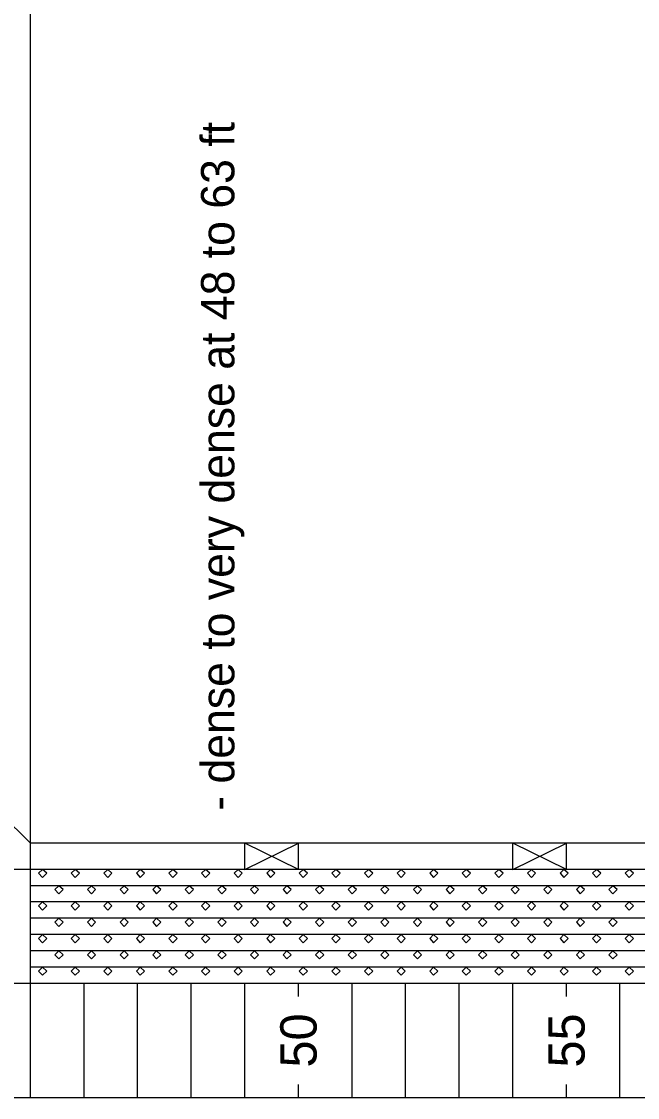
# Model space of a CAD drawing. Extents: x 1313964 to 1316843, y 2087046 to 2096619.
# Drawn here: x 1314089.13 to 1314100.62, y 2089873.43 to 2089893.52 of the extents above; entities that cross this region are included whole.
import ezdxf

# ---------------------------------------------------------------- set-up
doc = ezdxf.new("R2010")
doc.units = 0
doc.layers.add('B-Sub-Contour', color=7, linetype='Continuous')

msp = doc.modelspace()

# ---------------------------------------------------------------- linework, layer by layer
at = {"layer": 'B-Sub-Contour'}
for points in [[(1314136.725, 2089873.434), (1314136.725, 2089916.306), (1314075.306, 2089916.306), (1314075.306, 2089873.434), (1314136.725, 2089873.434)], [(1314089.292, 2089873.434), (1314089.292, 2089916.306)], [(1314089.292, 2089878.178), (1314088.745, 2089878.725)], [(1314134.292, 2089878.178), (1314089.292, 2089878.178)], [(1314093.292, 2089877.691), (1314094.292, 2089878.178)], [(1314094.292, 2089877.691), (1314093.292, 2089878.178)], [(1314093.292, 2089877.691), (1314093.292, 2089878.178)], [(1314094.292, 2089877.691), (1314094.292, 2089878.178)], [(1314098.292, 2089877.691), (1314099.292, 2089878.178)], [(1314099.292, 2089877.691), (1314098.292, 2089878.178)], [(1314098.292, 2089877.691), (1314098.292, 2089878.178)], [(1314099.292, 2089877.691), (1314099.292, 2089878.178)], [(1314134.292, 2089877.691), (1314082.603, 2089877.691)], [(1314112.292, 2089877.387), (1314089.292, 2089877.387)], [(1314112.292, 2089877.083), (1314089.292, 2089877.083)], [(1314112.292, 2089876.779), (1314089.292, 2089876.779)], [(1314112.292, 2089876.475), (1314089.292, 2089876.475)], [(1314112.292, 2089876.171), (1314089.292, 2089876.171)], [(1314112.292, 2089875.867), (1314089.292, 2089875.867)], [(1314134.292, 2089875.563), (1314082.603, 2089875.563)], [(1314089.292, 2089875.319), (1314089.292, 2089875.563)], [(1314090.292, 2089873.434), (1314090.292, 2089875.563)], [(1314090.292, 2089873.434), (1314090.292, 2089875.563)], [(1314091.292, 2089873.434), (1314091.292, 2089875.563)], [(1314092.292, 2089873.434), (1314092.292, 2089875.563)], [(1314092.292, 2089873.434), (1314092.292, 2089875.563)], [(1314093.292, 2089873.434), (1314093.292, 2089875.563)], [(1314094.292, 2089875.319), (1314094.292, 2089875.563)], [(1314094.292, 2089875.319), (1314094.292, 2089875.563)], [(1314095.292, 2089873.434), (1314095.292, 2089875.563)], [(1314096.292, 2089873.434), (1314096.292, 2089875.563)], [(1314096.292, 2089873.434), (1314096.292, 2089875.563)], [(1314097.292, 2089873.434), (1314097.292, 2089875.563)], [(1314098.292, 2089873.434), (1314098.292, 2089875.563)], [(1314098.292, 2089873.434), (1314098.292, 2089875.563)], [(1314099.292, 2089875.319), (1314099.292, 2089875.563)], [(1314100.292, 2089873.434), (1314100.292, 2089875.563)], [(1314100.292, 2089873.434), (1314100.292, 2089875.563)], [(1314089.292, 2089873.434), (1314089.292, 2089873.678)], [(1314094.292, 2089873.434), (1314094.292, 2089873.678)], [(1314094.292, 2089873.434), (1314094.292, 2089873.678)], [(1314099.292, 2089873.434), (1314099.292, 2089873.678)]]:
    msp.add_lwpolyline(points, dxfattribs=at)
for points in [[(1314089.517, 2089877.691), (1314089.444, 2089877.618), (1314089.517, 2089877.539), (1314089.597, 2089877.618)], [(1314090.126, 2089877.691), (1314090.053, 2089877.618), (1314090.126, 2089877.539), (1314090.205, 2089877.618)], [(1314090.734, 2089877.691), (1314090.661, 2089877.618), (1314090.734, 2089877.539), (1314090.813, 2089877.618)], [(1314091.342, 2089877.691), (1314091.269, 2089877.618), (1314091.342, 2089877.539), (1314091.421, 2089877.618)], [(1314091.95, 2089877.691), (1314091.877, 2089877.618), (1314091.95, 2089877.539), (1314092.029, 2089877.618)], [(1314092.558, 2089877.691), (1314092.485, 2089877.618), (1314092.558, 2089877.539), (1314092.637, 2089877.618)], [(1314093.166, 2089877.691), (1314093.093, 2089877.618), (1314093.166, 2089877.539), (1314093.245, 2089877.618)], [(1314093.774, 2089877.691), (1314093.701, 2089877.618), (1314093.774, 2089877.539), (1314093.853, 2089877.618)], [(1314094.382, 2089877.691), (1314094.309, 2089877.618), (1314094.382, 2089877.539), (1314094.461, 2089877.618)], [(1314094.99, 2089877.691), (1314094.917, 2089877.618), (1314094.99, 2089877.539), (1314095.069, 2089877.618)], [(1314095.599, 2089877.691), (1314095.526, 2089877.618), (1314095.599, 2089877.539), (1314095.678, 2089877.618)], [(1314096.207, 2089877.691), (1314096.134, 2089877.618), (1314096.207, 2089877.539), (1314096.286, 2089877.618)], [(1314096.815, 2089877.691), (1314096.742, 2089877.618), (1314096.815, 2089877.539), (1314096.894, 2089877.618)], [(1314097.423, 2089877.691), (1314097.35, 2089877.618), (1314097.423, 2089877.539), (1314097.502, 2089877.618)], [(1314098.031, 2089877.691), (1314097.958, 2089877.618), (1314098.031, 2089877.539), (1314098.11, 2089877.618)], [(1314098.639, 2089877.691), (1314098.566, 2089877.618), (1314098.639, 2089877.539), (1314098.718, 2089877.618)], [(1314099.247, 2089877.691), (1314099.174, 2089877.618), (1314099.247, 2089877.539), (1314099.326, 2089877.618)], [(1314099.855, 2089877.691), (1314099.782, 2089877.618), (1314099.855, 2089877.539), (1314099.934, 2089877.618)], [(1314100.463, 2089877.691), (1314100.39, 2089877.618), (1314100.463, 2089877.539), (1314100.542, 2089877.618)], [(1314089.822, 2089877.387), (1314089.749, 2089877.314), (1314089.822, 2089877.235), (1314089.901, 2089877.314)], [(1314090.43, 2089877.387), (1314090.357, 2089877.314), (1314090.43, 2089877.235), (1314090.509, 2089877.314)], [(1314091.038, 2089877.387), (1314090.965, 2089877.314), (1314091.038, 2089877.235), (1314091.117, 2089877.314)], [(1314091.646, 2089877.387), (1314091.573, 2089877.314), (1314091.646, 2089877.235), (1314091.725, 2089877.314)], [(1314092.254, 2089877.387), (1314092.181, 2089877.314), (1314092.254, 2089877.235), (1314092.333, 2089877.314)], [(1314092.862, 2089877.387), (1314092.789, 2089877.314), (1314092.862, 2089877.235), (1314092.941, 2089877.314)], [(1314093.47, 2089877.387), (1314093.397, 2089877.314), (1314093.47, 2089877.235), (1314093.549, 2089877.314)], [(1314094.078, 2089877.387), (1314094.005, 2089877.314), (1314094.078, 2089877.235), (1314094.157, 2089877.314)], [(1314094.686, 2089877.387), (1314094.613, 2089877.314), (1314094.686, 2089877.235), (1314094.765, 2089877.314)], [(1314095.294, 2089877.387), (1314095.221, 2089877.314), (1314095.294, 2089877.235), (1314095.374, 2089877.314)], [(1314095.903, 2089877.387), (1314095.83, 2089877.314), (1314095.903, 2089877.235), (1314095.982, 2089877.314)], [(1314096.511, 2089877.387), (1314096.438, 2089877.314), (1314096.511, 2089877.235), (1314096.59, 2089877.314)], [(1314097.119, 2089877.387), (1314097.046, 2089877.314), (1314097.119, 2089877.235), (1314097.198, 2089877.314)], [(1314097.727, 2089877.387), (1314097.654, 2089877.314), (1314097.727, 2089877.235), (1314097.806, 2089877.314)], [(1314098.335, 2089877.387), (1314098.262, 2089877.314), (1314098.335, 2089877.235), (1314098.414, 2089877.314)], [(1314098.943, 2089877.387), (1314098.87, 2089877.314), (1314098.943, 2089877.235), (1314099.022, 2089877.314)], [(1314099.551, 2089877.387), (1314099.478, 2089877.314), (1314099.551, 2089877.235), (1314099.63, 2089877.314)], [(1314100.159, 2089877.387), (1314100.086, 2089877.314), (1314100.159, 2089877.235), (1314100.238, 2089877.314)], [(1314089.517, 2089877.083), (1314089.444, 2089877.01), (1314089.517, 2089876.931), (1314089.597, 2089877.01)], [(1314090.126, 2089877.083), (1314090.053, 2089877.01), (1314090.126, 2089876.931), (1314090.205, 2089877.01)], [(1314090.734, 2089877.083), (1314090.661, 2089877.01), (1314090.734, 2089876.931), (1314090.813, 2089877.01)], [(1314091.342, 2089877.083), (1314091.269, 2089877.01), (1314091.342, 2089876.931), (1314091.421, 2089877.01)], [(1314091.95, 2089877.083), (1314091.877, 2089877.01), (1314091.95, 2089876.931), (1314092.029, 2089877.01)], [(1314092.558, 2089877.083), (1314092.485, 2089877.01), (1314092.558, 2089876.931), (1314092.637, 2089877.01)], [(1314093.166, 2089877.083), (1314093.093, 2089877.01), (1314093.166, 2089876.931), (1314093.245, 2089877.01)], [(1314093.774, 2089877.083), (1314093.701, 2089877.01), (1314093.774, 2089876.931), (1314093.853, 2089877.01)], [(1314094.382, 2089877.083), (1314094.309, 2089877.01), (1314094.382, 2089876.931), (1314094.461, 2089877.01)], [(1314094.99, 2089877.083), (1314094.917, 2089877.01), (1314094.99, 2089876.931), (1314095.069, 2089877.01)], [(1314095.599, 2089877.083), (1314095.526, 2089877.01), (1314095.599, 2089876.931), (1314095.678, 2089877.01)], [(1314096.207, 2089877.083), (1314096.134, 2089877.01), (1314096.207, 2089876.931), (1314096.286, 2089877.01)], [(1314096.815, 2089877.083), (1314096.742, 2089877.01), (1314096.815, 2089876.931), (1314096.894, 2089877.01)], [(1314097.423, 2089877.083), (1314097.35, 2089877.01), (1314097.423, 2089876.931), (1314097.502, 2089877.01)], [(1314098.031, 2089877.083), (1314097.958, 2089877.01), (1314098.031, 2089876.931), (1314098.11, 2089877.01)], [(1314098.639, 2089877.083), (1314098.566, 2089877.01), (1314098.639, 2089876.931), (1314098.718, 2089877.01)], [(1314099.247, 2089877.083), (1314099.174, 2089877.01), (1314099.247, 2089876.931), (1314099.326, 2089877.01)], [(1314099.855, 2089877.083), (1314099.782, 2089877.01), (1314099.855, 2089876.931), (1314099.934, 2089877.01)], [(1314100.463, 2089877.083), (1314100.39, 2089877.01), (1314100.463, 2089876.931), (1314100.542, 2089877.01)], [(1314089.822, 2089876.779), (1314089.749, 2089876.706), (1314089.822, 2089876.627), (1314089.901, 2089876.706)], [(1314090.43, 2089876.779), (1314090.357, 2089876.706), (1314090.43, 2089876.627), (1314090.509, 2089876.706)], [(1314091.038, 2089876.779), (1314090.965, 2089876.706), (1314091.038, 2089876.627), (1314091.117, 2089876.706)], [(1314091.646, 2089876.779), (1314091.573, 2089876.706), (1314091.646, 2089876.627), (1314091.725, 2089876.706)], [(1314092.254, 2089876.779), (1314092.181, 2089876.706), (1314092.254, 2089876.627), (1314092.333, 2089876.706)], [(1314092.862, 2089876.779), (1314092.789, 2089876.706), (1314092.862, 2089876.627), (1314092.941, 2089876.706)], [(1314093.47, 2089876.779), (1314093.397, 2089876.706), (1314093.47, 2089876.627), (1314093.549, 2089876.706)], [(1314094.078, 2089876.779), (1314094.005, 2089876.706), (1314094.078, 2089876.627), (1314094.157, 2089876.706)], [(1314094.686, 2089876.779), (1314094.613, 2089876.706), (1314094.686, 2089876.627), (1314094.765, 2089876.706)], [(1314095.294, 2089876.779), (1314095.221, 2089876.706), (1314095.294, 2089876.627), (1314095.374, 2089876.706)], [(1314095.903, 2089876.779), (1314095.83, 2089876.706), (1314095.903, 2089876.627), (1314095.982, 2089876.706)], [(1314096.511, 2089876.779), (1314096.438, 2089876.706), (1314096.511, 2089876.627), (1314096.59, 2089876.706)], [(1314097.119, 2089876.779), (1314097.046, 2089876.706), (1314097.119, 2089876.627), (1314097.198, 2089876.706)], [(1314097.727, 2089876.779), (1314097.654, 2089876.706), (1314097.727, 2089876.627), (1314097.806, 2089876.706)], [(1314098.335, 2089876.779), (1314098.262, 2089876.706), (1314098.335, 2089876.627), (1314098.414, 2089876.706)], [(1314098.943, 2089876.779), (1314098.87, 2089876.706), (1314098.943, 2089876.627), (1314099.022, 2089876.706)], [(1314099.551, 2089876.779), (1314099.478, 2089876.706), (1314099.551, 2089876.627), (1314099.63, 2089876.706)], [(1314100.159, 2089876.779), (1314100.086, 2089876.706), (1314100.159, 2089876.627), (1314100.238, 2089876.706)], [(1314089.517, 2089876.475), (1314089.444, 2089876.402), (1314089.517, 2089876.323), (1314089.597, 2089876.402)], [(1314090.126, 2089876.475), (1314090.053, 2089876.402), (1314090.126, 2089876.323), (1314090.205, 2089876.402)], [(1314090.734, 2089876.475), (1314090.661, 2089876.402), (1314090.734, 2089876.323), (1314090.813, 2089876.402)], [(1314091.342, 2089876.475), (1314091.269, 2089876.402), (1314091.342, 2089876.323), (1314091.421, 2089876.402)], [(1314091.95, 2089876.475), (1314091.877, 2089876.402), (1314091.95, 2089876.323), (1314092.029, 2089876.402)], [(1314092.558, 2089876.475), (1314092.485, 2089876.402), (1314092.558, 2089876.323), (1314092.637, 2089876.402)], [(1314093.166, 2089876.475), (1314093.093, 2089876.402), (1314093.166, 2089876.323), (1314093.245, 2089876.402)], [(1314093.774, 2089876.475), (1314093.701, 2089876.402), (1314093.774, 2089876.323), (1314093.853, 2089876.402)], [(1314094.382, 2089876.475), (1314094.309, 2089876.402), (1314094.382, 2089876.323), (1314094.461, 2089876.402)], [(1314094.99, 2089876.475), (1314094.917, 2089876.402), (1314094.99, 2089876.323), (1314095.069, 2089876.402)], [(1314095.599, 2089876.475), (1314095.526, 2089876.402), (1314095.599, 2089876.323), (1314095.678, 2089876.402)], [(1314096.207, 2089876.475), (1314096.134, 2089876.402), (1314096.207, 2089876.323), (1314096.286, 2089876.402)], [(1314096.815, 2089876.475), (1314096.742, 2089876.402), (1314096.815, 2089876.323), (1314096.894, 2089876.402)], [(1314097.423, 2089876.475), (1314097.35, 2089876.402), (1314097.423, 2089876.323), (1314097.502, 2089876.402)], [(1314098.031, 2089876.475), (1314097.958, 2089876.402), (1314098.031, 2089876.323), (1314098.11, 2089876.402)], [(1314098.639, 2089876.475), (1314098.566, 2089876.402), (1314098.639, 2089876.323), (1314098.718, 2089876.402)], [(1314099.247, 2089876.475), (1314099.174, 2089876.402), (1314099.247, 2089876.323), (1314099.326, 2089876.402)], [(1314099.855, 2089876.475), (1314099.782, 2089876.402), (1314099.855, 2089876.323), (1314099.934, 2089876.402)], [(1314100.463, 2089876.475), (1314100.39, 2089876.402), (1314100.463, 2089876.323), (1314100.542, 2089876.402)], [(1314089.822, 2089876.171), (1314089.749, 2089876.098), (1314089.822, 2089876.019), (1314089.901, 2089876.098)], [(1314090.43, 2089876.171), (1314090.357, 2089876.098), (1314090.43, 2089876.019), (1314090.509, 2089876.098)], [(1314091.038, 2089876.171), (1314090.965, 2089876.098), (1314091.038, 2089876.019), (1314091.117, 2089876.098)], [(1314091.646, 2089876.171), (1314091.573, 2089876.098), (1314091.646, 2089876.019), (1314091.725, 2089876.098)], [(1314092.254, 2089876.171), (1314092.181, 2089876.098), (1314092.254, 2089876.019), (1314092.333, 2089876.098)], [(1314092.862, 2089876.171), (1314092.789, 2089876.098), (1314092.862, 2089876.019), (1314092.941, 2089876.098)], [(1314093.47, 2089876.171), (1314093.397, 2089876.098), (1314093.47, 2089876.019), (1314093.549, 2089876.098)], [(1314094.078, 2089876.171), (1314094.005, 2089876.098), (1314094.078, 2089876.019), (1314094.157, 2089876.098)], [(1314094.686, 2089876.171), (1314094.613, 2089876.098), (1314094.686, 2089876.019), (1314094.765, 2089876.098)], [(1314095.294, 2089876.171), (1314095.221, 2089876.098), (1314095.294, 2089876.019), (1314095.374, 2089876.098)], [(1314095.903, 2089876.171), (1314095.83, 2089876.098), (1314095.903, 2089876.019), (1314095.982, 2089876.098)], [(1314096.511, 2089876.171), (1314096.438, 2089876.098), (1314096.511, 2089876.019), (1314096.59, 2089876.098)], [(1314097.119, 2089876.171), (1314097.046, 2089876.098), (1314097.119, 2089876.019), (1314097.198, 2089876.098)], [(1314097.727, 2089876.171), (1314097.654, 2089876.098), (1314097.727, 2089876.019), (1314097.806, 2089876.098)], [(1314098.335, 2089876.171), (1314098.262, 2089876.098), (1314098.335, 2089876.019), (1314098.414, 2089876.098)], [(1314098.943, 2089876.171), (1314098.87, 2089876.098), (1314098.943, 2089876.019), (1314099.022, 2089876.098)], [(1314099.551, 2089876.171), (1314099.478, 2089876.098), (1314099.551, 2089876.019), (1314099.63, 2089876.098)], [(1314100.159, 2089876.171), (1314100.086, 2089876.098), (1314100.159, 2089876.019), (1314100.238, 2089876.098)], [(1314089.517, 2089875.867), (1314089.444, 2089875.794), (1314089.517, 2089875.715), (1314089.597, 2089875.794)], [(1314090.126, 2089875.867), (1314090.053, 2089875.794), (1314090.126, 2089875.715), (1314090.205, 2089875.794)], [(1314090.734, 2089875.867), (1314090.661, 2089875.794), (1314090.734, 2089875.715), (1314090.813, 2089875.794)], [(1314091.342, 2089875.867), (1314091.269, 2089875.794), (1314091.342, 2089875.715), (1314091.421, 2089875.794)], [(1314091.95, 2089875.867), (1314091.877, 2089875.794), (1314091.95, 2089875.715), (1314092.029, 2089875.794)], [(1314092.558, 2089875.867), (1314092.485, 2089875.794), (1314092.558, 2089875.715), (1314092.637, 2089875.794)], [(1314093.166, 2089875.867), (1314093.093, 2089875.794), (1314093.166, 2089875.715), (1314093.245, 2089875.794)], [(1314093.774, 2089875.867), (1314093.701, 2089875.794), (1314093.774, 2089875.715), (1314093.853, 2089875.794)], [(1314094.382, 2089875.867), (1314094.309, 2089875.794), (1314094.382, 2089875.715), (1314094.461, 2089875.794)], [(1314094.99, 2089875.867), (1314094.917, 2089875.794), (1314094.99, 2089875.715), (1314095.069, 2089875.794)], [(1314095.599, 2089875.867), (1314095.526, 2089875.794), (1314095.599, 2089875.715), (1314095.678, 2089875.794)], [(1314096.207, 2089875.867), (1314096.134, 2089875.794), (1314096.207, 2089875.715), (1314096.286, 2089875.794)], [(1314096.815, 2089875.867), (1314096.742, 2089875.794), (1314096.815, 2089875.715), (1314096.894, 2089875.794)], [(1314097.423, 2089875.867), (1314097.35, 2089875.794), (1314097.423, 2089875.715), (1314097.502, 2089875.794)], [(1314098.031, 2089875.867), (1314097.958, 2089875.794), (1314098.031, 2089875.715), (1314098.11, 2089875.794)], [(1314098.639, 2089875.867), (1314098.566, 2089875.794), (1314098.639, 2089875.715), (1314098.718, 2089875.794)], [(1314099.247, 2089875.867), (1314099.174, 2089875.794), (1314099.247, 2089875.715), (1314099.326, 2089875.794)], [(1314099.855, 2089875.867), (1314099.782, 2089875.794), (1314099.855, 2089875.715), (1314099.934, 2089875.794)], [(1314100.463, 2089875.867), (1314100.39, 2089875.794), (1314100.463, 2089875.715), (1314100.542, 2089875.794)]]:
    msp.add_lwpolyline(points, close=True, dxfattribs=at)

# ---------------------------------------------------------------- texts
for s, height, p in [('- dense to very dense at 48 to 63 ft', 0.62209, (1314093.097, 2089878.786)), ('50', 0.6786, (1314094.632, 2089873.994)), ('50', 0.6786, (1314094.632, 2089873.994)), ('55', 0.6786, (1314099.632, 2089873.994))]:
    msp.add_text(s, height=height, rotation=90, dxfattribs=at).set_placement(p)

doc.saveas('drawing.dxf')
